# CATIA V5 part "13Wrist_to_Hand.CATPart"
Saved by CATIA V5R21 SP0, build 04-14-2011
Part number: Wrist_to_Hand
Bounding box of the stored display mesh (mm): x -25 to 5, y -16.902 to 24.098, z -24.703 to 25.297
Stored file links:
  F:\教程\Robotic_Arm_Arduino_Kinect\机械臂CAD\Arm_Detailed_Design\Wrist_to_Hand.CATPart
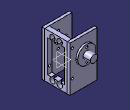
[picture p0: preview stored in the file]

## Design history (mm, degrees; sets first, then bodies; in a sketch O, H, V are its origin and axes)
Body1 "Plate1" (main body)
  Sketch1 on yz-plane, origin (0, 0, 0), H (0, 1, 0), V (0, 0, 1)
    line L1 (-13.9025, 25.2974) -> (11.0975, 25.2974)
    line L2 (11.0975, 25.2974) -> (11.0975, -24.7026)
    line L3 (11.0975, -24.7026) -> (-13.9025, -24.7026)
    line L4 (-13.9025, -24.7026) -> (-13.9025, 25.2974)
    arc A1 centre (-5.4025, -20.2026) radius 3 from (-6.6014, -17.4526) to (-4.2035, -17.4526) ccw
    point P5 (-5.4025, -20.2026)
    arc A2 centre (2.5975, -20.2026) radius 3 from (1.3986, -17.4526) to (3.7965, -17.4526) ccw
    point P6 (2.5975, -20.2026)
    axis line L5 (-30.6382, 0.2974) -> (38.767, 0.2974)
    arc A3 centre (2.5975, 20.7974) radius 3 from (1.3986, 18.0474) to (3.7965, 18.0474) cw
    arc A4 centre (-5.4025, 20.7974) radius 3 from (-6.6014, 18.0474) to (-4.2035, 18.0474) cw
    line L6 (-10.9025, 18.0474) -> (-6.6014, 18.0474)
    line L7 (8.0975, 18.0474) -> (8.0975, -17.4526)
    line L8 (8.0975, -17.4526) -> (3.7965, -17.4526)
    line L9 (-10.9025, -17.4526) -> (-10.9025, 18.0474)
    point P16 (1.3986, -17.4526)
    line L10 (1.3986, -17.4526) -> (-4.2035, -17.4526)
    point P18 (-6.6014, -17.4526)
    line L11 (-6.6014, -17.4526) -> (-10.9025, -17.4526)
    point P20 (-4.2035, 18.0474)
    line L12 (-4.2035, 18.0474) -> (1.3986, 18.0474)
    point P22 (3.7965, 18.0474)
    line L13 (3.7965, 18.0474) -> (8.0975, 18.0474)
    length L1 = 25
    length L2 = 50
    distance P5 L3 = 4.5
    distance P6 L3 = 4.5
    distance P5 P6 = 8
    radius A1 = 3
    radius A2 = 3
    distance P5 L4 = 8.5
    distance L5 L3 = 25
    distance L3 L8 = 7.25
    distance L6 L1 = 7.25
    distance L7 L2 = 3
    distance L9 L4 = 3
    horizontal: L1 H, L3 H, L5 H, L6 H, L8 H, L10 H, L11 H, L12 H, L13 H
    vertical: L2 V, L4 V, L7 V, L9 V
    symmetry: A2 A3 L5, A1 A4 L5
    coincidence: L8 P16, L8 L10, L10 P18, L10 L11, L6 P20, L6 L12, L12 P22, L12 L13
  Pad1: profile Sketch1, direction (1, 0, 0), length 5
  Sketch2 on face of Pad1 from Sketch1.L4, origin (0, -13.9025, 0), H (1, 0, 0), V (0, 0, 1)
    circle A1 centre (2.5, 19.2974) radius 1.25
    point P1 (2.5, 19.2974)
    circle A2 centre (2.5, -9.7026) radius 1.25
    point P2 (2.5, -9.7026)
    reference projected line E1 (0, -24.7026) -> (5, -24.7026) from edge [face of Pad1 from Sketch1.L3 | face of Pad1 from Sketch1.L4]
    reference projected line E2 (0, 25.2974) -> (0, -24.7026) from edge [start face of Pad1 | face of Pad1 from Sketch1.L4]
    reference projected line E3 (0, 25.2974) -> (5, 25.2974) from edge [face of Pad1 from Sketch1.L4 | face of Pad1 from Sketch1.L1]
    reference projected line E4 (0, 25.2974) -> (0, -24.7026) from edge [start face of Pad1 | face of Pad1 from Sketch1.L4]
    radius A2 = 1.25
    distance P2 E1 = 15
    distance P2 E2 = 2.5
    distance P1 E3 = 6
    radius A1 = 1.25
    distance P1 E4 = 2.5
  Pocket1: profile Sketch2, direction (0, 1, 0), length 4
  Sketch3 on face of Pad1 from Sketch1.L2, origin (0, 11.0975, 0), H (-1, 0, 0), V (0, 0, 1)
    circle A1 centre (-2.5, 19.2974) radius 1.25
    point P1 (-2.5, 19.2974)
    circle A2 centre (-2.5, -9.7026) radius 1.25
    point P2 (-2.5, -9.7026)
    reference projected line E1 (0, -24.7026) -> (-5, -24.7026) from edge [face of Pad1 from Sketch1.L2 | face of Pad1 from Sketch1.L3]
    reference projected line E2 (-5, -24.7026) -> (-5, 25.2974) from edge [face of Pad1 from Sketch1.L2 | end face of Pad1]
    reference projected line E3 (-5, -24.7026) -> (-5, 25.2974) from edge [face of Pad1 from Sketch1.L2 | end face of Pad1]
    reference projected line E4 (0, 25.2974) -> (-5, 25.2974) from edge [face of Pad1 from Sketch1.L1 | face of Pad1 from Sketch1.L2]
    radius A2 = 1.25
    distance P2 E1 = 15
    distance P2 E2 = 2.5
    distance P1 E3 = 2.5
    radius A1 = 1.25
    distance P1 E4 = 6
  Pocket2: profile Sketch3, direction (0, -1, 0), length 4
Body2 "Plate2"
  Sketch4 on face of Pad1 from Sketch1.L4, origin (0, -13.9025, 0), H (1, 0, 0), V (0, 0, 1)
    line L1 (-25, 25.2974) -> (5, 25.2974)
    line L2 (5, 25.2974) -> (5, -24.7026)
    line L3 (5, -24.7026) -> (-25, -24.7026)
    line L4 (-25, -24.7026) -> (-25, 25.2974)
    reference projected line E1 (0, 25.2974) -> (5, 25.2974) from edge [face of Pad1 from Sketch1.L4 | face of Pad1 from Sketch1.L1]
    reference projected line E2 (0, -24.7026) -> (5, -24.7026) from edge [face of Pad1 from Sketch1.L3 | face of Pad1 from Sketch1.L4]
    reference projected line E3 (5, 25.2974) -> (5, -24.7026) from edge [face of Pad1 from Sketch1.L4 | end face of Pad1]
    circle A1 centre (-10, 7.0474) radius 4
    point P5 (-10, 7.0474)
    circle A2 centre (-10, 15.5474) radius 1.25
    point P6 (-10, 15.5474)
    circle A3 centre (2.5, 19.2974) radius 1.25
    point P7 (2.5, 19.2974)
    circle A4 centre (2.5, -9.7026) radius 1.25
    point P8 (2.5, -9.7026)
    circle A5 centre (-18.5, 7.0474) radius 1.25
    circle A6 centre (-10, -1.4526) radius 1.25
    circle A7 centre (-1.5, 7.0474) radius 1.25
    distance L2 L4 = 30
    distance P5 L2 = 15
    distance P5 L1 = 18.25
    radius A1 = 4
    radius A2 = 1.25
    distance P6 P5 = 8.5
    distance P6 L2 = 15
    radius A4 = 1.25
    distance P8 L2 = 2.5
    distance P8 L3 = 15
    radius A3 = 1.25
    distance P7 L1 = 6
    distance P7 L2 = 2.5
    horizontal: L1 H, L3 H
    vertical: L2 V, L4 V
    coincidence: L1 E1, L3 E2, L2 E3
  Pad2: profile Sketch4, direction (0, -1, 0), length 3
Body3 "Plate3"
  Sketch5 on face of Pad1 from Sketch1.L2, origin (0, 11.0975, 0), H (-1, 0, 0), V (0, 0, 1)
    line L1 (-5, 25.2974) -> (25, 25.2974)
    line L2 (25, 25.2974) -> (25, -24.7026)
    line L3 (25, -24.7026) -> (-5, -24.7026)
    line L4 (-5, -24.7026) -> (-5, 25.2974)
    construction circle A1 centre (11.5, 7.0474) radius 10
    point P5 (11.5, 7.0474)
    reference projected line E1 (-5, 25.2974) -> (25, 25.2974) from edge [start face of Pad2 | face of Pad2 from Sketch4.L1]
    reference projected line E2 (25, -24.7026) -> (-5, -24.7026) from edge [start face of Pad2 | face of Pad2 from Sketch4.L3]
    reference projected line E3 (-5, -24.7026) -> (-5, 25.2974) from edge [face of Pad1 from Sketch1.L2 | end face of Pad1]
    circle A2 centre (-2.5, 19.2974) radius 1.25
    point P6 (-2.5, 19.2974)
    circle A3 centre (-2.5, -9.7026) radius 1.25
    point P7 (-2.5, -9.7026)
    circle A4 centre (11.5, 14.0474) radius 1.25
    point P8 (11.5, 14.0474)
    circle A5 centre (11.5, 0.0474) radius 1.25
    point P9 (11.5, 0.0474)
    distance P5 L1 = 18.25
    distance P5 L4 = 16.5
    length L3 = 30
    radius A3 = 1.25
    distance P7 L3 = 15
    distance P7 L4 = 2.5
    distance P6 L4 = 2.5
    radius A2 = 1.25
    distance P6 L1 = 6
    radius A1 = 10
    distance P9 L4 = 16.5
    distance L4 P8 = 16.5
    distance P5 P8 = 7
    distance P9 P5 = 7
    radius A5 = 1.25
    radius A4 = 1.25
    horizontal: L1 H, L3 H
    vertical: L2 V, L4 V
    coincidence: L1 E1, L3 E2, L4 E3
  Pad3: profile Sketch5, direction (0, 1, 0), length 3
Body4 "Connect"
  Sketch6 on end face of Pad3, origin (0, 14.0975, 0), H (-1, 0, 0), V (0, 0, 1)
    circle A1 centre (11.5, 7.0474) radius 10
    point P1 (11.5, 7.0474)
    reference projected line E1 (25, 25.2974) -> (-5, 25.2974) from edge [face of Pad3 from Sketch5.L1 | end face of Pad3]
    reference projected line E2 (-5, 25.2974) -> (-5, -24.7026) from edge [face of Pad3 from Sketch5.L4 | end face of Pad3]
    circle A2 centre (11.5, 14.0474) radius 1.25
    point P2 (11.5, 14.0474)
    circle A3 centre (11.5, 0.0474) radius 1.25
    point P3 (11.5, 0.0474)
    reference projected line E3 (-5, 25.2974) -> (-5, -24.7026) from edge [face of Pad3 from Sketch5.L4 | end face of Pad3]
    reference projected line E4 (-5, 25.2974) -> (-5, -24.7026) from edge [face of Pad3 from Sketch5.L4 | end face of Pad3]
    radius A1 = 10
    distance P1 E1 = 18.25
    distance P1 E2 = 16.5
    radius A2 = 1.25
    radius A3 = 1.25
    distance P3 P1 = 7
    distance P2 P1 = 7
    distance P3 E3 = 16.5
    distance P2 E4 = 16.5
  Pad4: profile Sketch6, direction (0, 1, 0), length 2
  Sketch7 on end face of Pad4, origin (0, 16.0975, 0), H (-1, 0, 0), V (0, 0, 1)
    circle A1 centre (11.5, 7.0474) radius 4
    reference projected circle E1 centre (11.5, 7.0474) radius 10 from edge [face of Pad4 from Sketch6.A1 | end face of Pad4]
    radius A1 = 4
    concentricity: A1 E1
  Pad5: profile Sketch7, direction (0, 1, 0), length 8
